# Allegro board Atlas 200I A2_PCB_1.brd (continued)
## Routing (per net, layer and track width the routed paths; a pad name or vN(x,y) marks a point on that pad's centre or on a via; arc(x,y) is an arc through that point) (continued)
V_3V3_USBHUB0: length 137.8
  TOP w0.203: C207.1 88.93,75 88.78,74.85 88.37,74.85 88.11,74.6 R467.1 ; 90.04,76.59 90.04,77.41 90.46,77.82 U36.73 ; U36.22 99.27,77.42 ; C206.1 97.16,85.95 96.06,85.95 95.35,85.24 U36.48 ; v1(92.89,74.55) 92.89,75.14 92.95,75.2 U36.4 92.95,76.18 93.25,76.48 ; v1(73.53,91.57) R547.2
  TOP w0.254: R460.1 88.16,70.05 88.37,69.85 v1(89.23,69.85) ; R460.1 R546.1 ; R460.1 88.54,70.36 88.75,70.56 88.75,72.87 88.27,73.36 88.27,74.14 R467.1 ; v1(96.16,90.04) 96.34,90.22 98.02,90.22 98.3,89.94 98.3,86.66 98.09,86.46 C206.1 ; 90.04,76.59 v1(90.04,76.07) 89.41,75.44 C207.1 ; C208.1 92.79,74.45 v1(92.89,74.55) ; 93.25,76.48 93.9,76.48 94.51,77.09 96.15,77.09 96.81,76.43 98.28,76.43 99.27,77.42 ; 88.27,90.32 94.01,90.32 ; v1(101.54,79.49) 101.38,79.32 R649.1
  TOP w0.381: R640.1 21.04,111.3 v1(21.05,111.3) ; 88.27,90.32 87.5,89.56 87.5,88.47 85.99,86.96 79.01,86.96 78.49,87.48 76.66,87.48 73.53,90.6 v1(73.53,91.57) ; R551.2 v1(105.26,85.7) ; 94.01,90.32 94.59,89.74 ; v1(82.63,69.22) 82.63,69.67 82.35,69.95 R643.1
  ART03 w0.381: v1(90.04,76.07) 90.04,75.03 90.53,74.55 v1(92.89,74.55) ; v1(66.37,96.74) 64.5,98.62 49.12,98.62 45.4,102.33 30.17,102.33 21.2,111.3 v1(21.05,111.3) ; v1(101.42,75.97) 101.54,76.09 v1(101.54,79.49)
  ART04 w0.381: v1(73.53,91.57) 72.62,92.48 70.64,92.48 v1(66.37,96.74)
  BOTTOM w0.381: v1(82.63,69.22) 83.26,69.85 v1(89.23,69.85)
  vias: v1(95.91,89.59) v1(103.68,93.4) v1(103.68,92.76) v1(104.67,74.68) v1(105.94,74.68)
V_5V0_HUB:
  vias: v1(83.85,106.68) v1(84.61,106.68) v1(93.65,104.04)
V_12V0_CON_IN_F: length 62.2
  TOP w0.254: v1(109.37,41.28) 109.24,41.14 R374.2 108.01,41.14 107.88,41.27 C226.1 106.91,41.27 106.38,40.74 106.38,40.56 106.09,40.28 U12.9
  TOP w0.381: R382.1 109.04,21.39 v1(108.58,21.85) ; R371.2 100.22,42.06 100.43,41.85 101.96,41.85 102.84,40.97 102.84,37.74 102.69,37.59 v1(102.69,36.02)
  ART03 w0.381: v1(102.69,36.02) 102.69,24.13 104.04,22.78 112.67,22.78 v1(113.16,22.3)
  BOTTOM w0.254: v1(109.37,41.28) 109.11,41.02 108.35,41.02 107.8,40.46 107.8,31.92 109.47,30.25 109.47,21.82 109.22,21.56 108.86,21.56 v1(108.58,21.85)
V_12V0_SENSE: length 26
  TOP w0.254: R380.2 109.29,40.33 v1(109.35,40.27)
  TOP w0.381: v1(108.58,20.92) 108.11,21.39 R382.2
  BOTTOM w0.254: v1(109.35,40.27) 109.08,40.54 108.45,40.54 108.18,40.27 108.18,32.08 109.86,30.4 109.86,21.66 109.38,21.18 108.84,21.18 v1(108.58,20.92)
  vias: v1(104.88,27.26) v1(104.88,25.99) v1(104.88,24.38) v1(106.15,27.26) v1(106.15,25.99) v1(106.15,24.38) v1(107.42,27.26) v1(107.42,25.99) v1(107.42,24.38)
V_AVDD_1V0_PHY0: length 4.8
  TOP w0.203: v1(12.78,49.81) 12.78,49.83 12.75,49.86 U1.9 ; v1(7.97,51.44) 8.33,51.79 U1.47 ; v1(10.69,49.81) 10.75,49.88 U1.4
  TOP w0.254: v1(12.78,49.81) C53.2 ; v1(7.97,51.44) C52.2 ; C56.2 10.69,49.35 v1(10.69,49.81)
  vias: v1(6.6,68.45) v1(7.44,68.43)
V_AVDD_1V0_PHY1: length 6.2
  TOP w0.203: U2.4 56.91,30.84 ; U2.9 58.91,30.84 ; U2.47 54.56,32.36
  TOP w0.254: v1(54.74,31.14) 54.43,31.45 C71.2 54.1,31.9 54.56,32.36 ; 56.91,30.84 v1(56.91,30.27) 56.91,30.01 C72.2 ; C73.2 59.49,29.69 v1(58.91,30.27) 58.91,30.84
  vias: v1(52.43,27.79)
V_AVDD_3V3_PHY0: length 11.8
  TOP w0.203: U1.12 14.44,50.71 ; v1(8.1,50.27) 9.35,50.27 9.55,50.47 U1.1
  TOP w0.254: C50.2 7.36,50.06 7.36,50.07 C49.2 8.02,50.34 v1(8.1,50.27) ; 14.44,50.71 14.61,50.54 v1(14.61,50.39) C51.2
  ART04 w0.254: v1(14.61,50.39) 14.27,50.73 8.56,50.73 v1(8.1,50.27)
V_AVDD_3V3_PHY1: length 18.1
  TOP w0.203: 60.41,31.29 U2.12 ; 54.74,30.07 55.04,30.07 55.71,30.75 U2.1
  TOP w0.254: 54.74,30.07 C76.2 C77.2 52.66,29.47 v1(52.4,29.21) 52.36,29.17 LB5.2 ; 60.41,31.29 v1(60.73,30.96) 62.08,30.96 C75.2
  ART03 w0.254: v1(60.73,30.96) 56.36,30.96 55.32,32 54.37,32 53.49,31.12 53.49,30.3 v1(52.4,29.21)
V_BAT_3V0: length 104.3
  TOP w0.254: J16.283 107.5,56.95 108.2,57.66 v1(108.71,57.66)
  TOP w0.381: D1.3 20.42,75.44 v1(20.43,75.43)
  ART04 w0.381: v1(64.57,61.35) 53,72.92 51.81,72.92 51.11,72.22 25.71,72.22 25.39,72.54 25.39,72.63 24.67,73.34 22.52,73.34 v1(20.43,75.43)
  BOTTOM w0.254: v1(64.57,61.35) 66.08,61.35 67.02,60.41 67.02,58.88 67.3,58.6 69.2,58.6 74.05,63.45 98,63.45 101.3,60.15 104.03,58.37 108,58.37 v1(108.71,57.66)
V_DV11_HUB: length 26.8
  TOP w0.203: U38.40 83.21,101.37 83.13,101.45 82.3,101.45 ; U38.12 92.25,98.97 92.05,99.17 ; v1(88.01,92.96) 88.29,93.24 U38.67 ; 91.09,101.92 U38.22 91.09,103.44 91.29,103.64 ; U38.61 85.89,93.17 85.69,92.96 v1(85.34,92.96) ; U38.70 89.49,94.45 v1(89.6,94.56) ; v1(82.93,97.54) 83.19,97.54 83.42,97.77 U38.49 ; U38.46 83.32,98.97
  TOP w0.254: 91.09,101.92 91.19,101.83 91.82,101.83 92.05,101.6 92.05,99.17 ; v1(82.93,97.54) 82.45,97.54 C331.1 ; 91.29,103.64 91.92,104.27 C334.1 ; v1(88.01,92.96) 88.01,92.96 88.01,92.33 ; v1(85.34,92.96) 85.27,92.89 85.27,92.33 ; 83.32,98.97 83.02,99.28 82.48,99.28 v1(82.16,99.59) 81.93,99.82 C330.1
  BOTTOM w0.381: v1(88.01,92.96) 88.75,93.7 92.71,93.7 93.04,93.37 93.04,92.91 93.5,92.46 95.86,92.46 v1(96.04,92.28)
  vias: v1(76.96,99.19) v1(76.96,97.92) v1(76.96,96.65) v1(76.96,95.38) v1(76.96,94.11) v1(76.96,92.84) v1(76.96,91.57) v1(76.96,90.3) v1(76.96,89.03) v1(96.71,99.16)
V_DV12_HUB: length 18.2
  TOP w0.203: U36.64 91.69,81.42 ; U36.50 94.55,84.18 94.68,84.05 94.83,84.05 94.95,84.17 U36.49 94.95,85.42 95.99,86.46 ; U36.3 92.55,75.36 92.35,75.16 ; U36.58 91.55,83.82 ; U36.7 94.15,74.98 v1(94.25,74.88) ; 91.5,79.02 U36.70
  TOP w0.254: 95.99,86.46 C227.1 96.87,86.46 v1(96.96,86.55) ; 91.55,83.82 92.24,83.13 92.24,81.57 v1(92.06,81.38) 91.73,81.38 91.69,81.42 ; C279.1 91.06,74.88 v1(91.34,75.16) 92.35,75.16 ; 91.5,79.02 91.73,78.79 v1(91.73,78.31)
  BOTTOM w0.381: v1(92.06,81.38) 92.68,80.75 92.68,78.77 92.23,78.31 v1(91.73,78.31)
  vias: v1(98.63,74.9) v1(99.9,74.9) v1(101.54,80.42) v1(102.21,79.07)
V_DV33_HUB: length 120
  TOP w0.203: v1(87,92.96) 87,93.17 87.09,93.26 U38.64 ; U38.52 83.39,96.57 83.19,96.77 v1(82.93,96.77) ; U38.6 92.01,96.57 v1(91.9,96.69) ; U38.15 v1(93.55,100.17) ; U38.58 84.69,93.2 v1(84.45,92.96) ; U38.29 88.29,103.05 ; 82.93,100.17 U38.43 ; U38.73 90.69,94.45 v1(90.81,94.56)
  TOP w0.254: LB20.2 92.86,107.24 91.85,108.25 90.25,108.25 89.38,107.39 R639.1 88.98,106.93 88.85,107.06 C332.2 88.47,107.06 88.14,106.73 88.14,106.05 88.52,105.66 R598.2 88.21,105.31 87.91,105 87.91,104.01 88.28,103.64 R651.1 88.57,103.33 88.29,103.05 ; 86.18,92.33 87.09,92.33 87.09,92.87 v1(87,92.96) ; 84.35,92.33 84.35,92.86 v1(84.45,92.96) ; C335.1 81.91,100.84 82.16,100.59 v1(82.16,100.36) 82.46,100.06 R652.2 82.93,100.17 ; C353.2 82.45,96.77 v1(82.93,96.77) ; R646.2 94.97,100.91 94.77,100.71 94.36,100.71 94.16,100.51 C327.2 93.6,100.12 v1(93.55,100.17)
  TOP w0.381: R576.2 R577.2 v1(79.38,104.78) ; R642.1 v1(31.62,118.24)
  ART03 w0.381: v1(82.16,100.36) 82.34,100.36 82.72,99.97 82.72,99.19 83.54,98.38 83.54,97.37 83.16,96.99 83.15,96.99 v1(82.93,96.77) ; v1(31.62,118.24) 32.56,118.24 36.07,114.73 36.07,114.5 36.16,114.42 36.16,108.55 36.27,108.43 36.27,108.18 39.88,104.57 46.29,104.57 49.17,101.69 66.84,101.69 69.93,104.78 v1(79.38,104.78) 83.11,108.51 87.46,108.51 87.82,108.15 89.64,108.15 90.57,109.08 91.7,109.08 92.52,108.26 92.52,107.97 95.33,105.15 96.98,105.15 v1(97.22,104.91)
  ART04 w0.381: v1(79.38,104.78) 79.38,104.13 82.16,101.34 v1(82.16,100.36)
  vias: v1(97.22,104.33)
V_DVDD_1V0_PHY0: length 4.8
  TOP w0.203: U1.22 16.1,54.99
  TOP w0.254: 16.1,54.99 16.34,54.99 v1(17.83,56.49) 18.08,56.74 C57.2
  vias: v1(9.6,68.43) v1(10.87,68.43)
V_DVDD_1V0_PHY1: length 38.3
  TOP w0.203: U2.22 61.4,35.56 62.3,36.47 C70.2
  TOP w0.254: C70.2 62.8,36.61 v1(63.3,37.11)
  ART03 w0.381: v1(50.25,28.55) 50.04,28.77 48.69,28.77 46.24,31.22 46.24,36.76 46.55,37.06 46.55,37.53 v1(45.97,38.1)
  BOTTOM w0.381: v1(45.97,38.1) 46.16,38.29 47.25,38.29 47.98,39.03 48.58,39.03 49.8,40.25 51.68,40.25 52.08,39.84 53.76,39.84 v1(55.65,41.73) 55.65,39.85 58.13,37.38 59.85,37.38 60.63,36.59 60.96,36.46 62.64,36.46 v1(63.3,37.11)
V_STBY_1V8: length 364.8
  TOP w0.203: C132.1 v1(117.66,81.93) ; R569.1 v1(70.35,71.01) ; v1(109.58,89.39) 109.58,89.38 R239.2 ; v1(73,73.05) 72.92,72.97 R568.1 ; v1(109.24,76.34) 109.27,76.32 109.86,76.32
  TOP w0.254: 88.16,118.59 88.67,118.59 v1(88.77,118.49) 89,118.26 U18.1 ; 88.16,118.59 R496.1 ; 88.16,118.59 C292.2 ; v1(117.66,81.93) 118.11,82.38 U35.1 ; U22.1 93.46,112.59 93.04,112.17 C136.2 v1(93.78,110.41) ; R396.2 89.24,37.45 U15.1 ; v1(54.61,66.04) 54.38,66.27 R88.1 R87.1 ; R464.2 v1(126.38,21.26) ; v1(92.2,44.35) 92.46,44.6 R703.1 R704.1 ; v1(46,37.29) 46.02,37.31 R116.1 ; R552.2 125.2,88.03 v1(125.22,88.01) ; U33.1 112.4,70.1 C304.1 ; J2.64 6.42,83.26 v1(5.85,82.69) ; Q2.2 55.05,96.45 v1(55.12,96.52) C83.2 R197.2 ; R571.1 R565.1 96.57,60.44 96.08,60.93 96.08,64 96.72,64.95 102.53,70.76 109.88,70.76 110.34,70.31 ; v1(100.2,114.05) R601.1 R602.1 100,115.06 100.31,115.37 R611.1 R610.1 100.31,117.79 101.11,118.59 v1(103.16,118.59) C138.2 103.32,117.98 103.87,117.43 U23.1 ; R553.2 120.76,79.22 v1(120.5,78.96) ; 110.77,58.14 C299.1 111.86,58.14 112.52,58.8 U32.1 ; v1(125.48,50.01) 127.91,47.57 133.38,47.57 133.78,47.17 133.78,43.58 R469.2 ; R591.2 115.19,67.55 v1(114.93,67.29) ; v1(2.54,106.05) 2.44,105.94 R49.2 ; R254.1 v1(125.81,42.16) ; R12.1 118.4,69.93 118.1,70.22 U21.1 ; v1(68.83,33.15) 68.83,35.03 R156.1 ; R466.2 v1(128.83,26.85) ; R497.1 88.75,115.09 89.1,115.44 92.42,115.44 v1(92.51,115.53) ; C298.1 118.43,58.56 U20.1 118.43,62.36 117.75,63.04 ; R354.2 v1(111.99,107.24) ; v1(125.58,24.86) 125.57,24.86 R15.1 ; v1(114.8,78.96) 115.06,79.22 R629.2 ; R347.2 v1(125.53,112.03) ; R239.2 108.71,88.77 108.48,88.54 108.48,86.49 109.83,85.14 111.89,85.14 112.4,84.62 U34.1 112.4,82.32 111.96,81.87 C131.1 ; R589.2 v1(125.2,64.66) ; R462.2 v1(128.83,32.44)
  TOP w0.381: R295.2 R294.2 R293.2 R292.2 126.09,58.12 v1(126.09,58.12) ; R66.2 4.11,106.17 4.67,106.73 6.1,106.73 ; R50.2 6.1,106.73 ; 6.1,106.73 7.32,106.73 7.87,106.17 v1(7.87,106.07) 7.72,105.92 R67.2 ; R12.1 C296.1 117.51,72.87 116.96,73.42 112.38,73.42 110.16,71.2 ; 110.57,70.87 111.25,70.87 111.66,70.46 111.66,69.95 C304.1 ; R80.1 22.23,88.32 21.49,89.05 20.65,89.05 20.14,89.56 20.14,90.35 v1(19.68,90.81) ; R42.1 v1(6.48,74.8)
  ART03 w0.254: v1(71.82,75.87) 72.92,74.77 72.92,73.66 73,73.58 v1(73,73.05) 72.65,72.71 72.58,72.71 72.08,72.21 70.74,72.21 70.35,71.83 v1(70.35,71.01) ; v1(111.99,107.24) 111.99,106.49 113.26,105.22 113.26,102.78 112.31,101.83 112.09,101.83 111.81,101.55 111.81,92.1 111.1,91.39 111.1,90.91 v1(109.58,89.39) ; v1(55.12,96.52) 53.57,98.07 48.85,98.07 45.16,101.77 29.72,101.77 26.46,105.03 21.49,105.03 21.23,104.78 17.99,104.78 15.8,106.96 3.45,106.96 v1(2.54,106.05)
  ART03 w0.381: v1(6.48,74.8) 6.48,76.09 5.96,76.6 5.96,82.58 v1(5.85,82.69)
  ART04 w0.254: v1(120.5,78.96) 120,78.45 117.92,78.45 117.41,78.96 v1(114.8,78.96) ; v1(128.83,26.85) v1(128.83,32.44) ; v1(54.61,66.04) 55.73,66.04 63.9,57.86 63.9,56.65 64.24,56.31 64.24,52.53 66.67,50.09 66.67,45.64 68.52,43.8 69.42,43.8 70.12,43.09 70.18,42.95 70.18,34.49 v1(68.83,33.15) ; v1(92.53,39.29) 92.53,39.74 92.2,40.07 v1(92.2,44.35)
  BOTTOM w0.254: 122.91,48.69 122.94,48.67 ; v1(109.58,89.39) 109.57,89.38 108.7,89.38 107.37,88.05 107.37,78.79 109.24,76.91 v1(109.24,76.34) ; 81.57,21.43 80.73,21.43 79.88,22.28 76.2,22.28 70.76,27.72 70.76,28.77 69.52,30.01 69.52,32.46 v1(68.83,33.15) 68.2,33.78 62.43,33.78 59.45,36.75 58.02,36.75 56.11,38.66 52.53,38.66 51.46,39.73 50.16,39.73 48.21,37.77 46.48,37.77 v1(46,37.29) ; v1(128.83,32.44) 127.58,32.44 ; 121.56,70.13 120.62,69.19 120.62,67.94 120.14,67.46 120.14,67.03 119.46,66.34 115.87,66.34 v1(114.93,67.29)
  vias: v1(72.14,86.59) v1(72.77,86.59) v1(91.26,39.29) v1(91.89,39.29) v1(123.57,50.01) v1(124.21,50.01) v1(124.84,50.01) v1(127.74,34.82) v1(128.3,34.82)
V_STBY_3V3: length 228.6
  TOP w0.254: C300.2 117.41,67.27 v1(118.44,67.27) 118.44,65.91 U20.14 ; R113.2 122.17,104.32 122.17,103.7 R484.1 R483.1 R485.1 122.28,100.91 124.28,100.91 124.43,100.76 ; v1(48.44,29.79) 48.31,29.67 R647.2 ; v1(111.83,29.75) R34.2 R33.2 ; C17.2 75.74,82.43 U25.14 78.58,82.43 78.97,82.04 ; C137.1 v1(110.17,118.36) 110.17,117.69 109.92,117.43 U23.8 ; v1(100.22,118.38) R494.2 R495.2 99.47,117.33 R489.1 ; R236.1 R238.1 124.97,77.23 v1(125.09,77.36) ; U32.14 112.52,66.65 v1(111.89,67.29) 111.43,67.75 111.43,68.36 C301.2 ; C16.2 113.08,38.51 112.83,38.25 R24.2 ; J10.51 v1(2.05,73.65) ; C133.1 88.6,111.53 v1(88.7,111.63) 89.51,111.63 89.96,112.08 U22.8 ; C140.2 117.21,78.94 v1(118.11,78.94) 118.11,77.58 U21.14 ; R41.1 5.61,74.14 v1(4.82,73.35) J10.50 ; C129.2 v1(111.2,87.25) 111.73,87.25 112.4,87.92 U34.14 ; U19.24 110.96,92.09 C293.1 ; C291.1 95.77,118.38 v1(95.76,118.36) 95.65,118.26 U18.8 ; 78.97,82.04 78.97,78.91 78.61,78.55 78.61,77.11 78.01,76.51 U24.14 75.62,76.51 C139.2 ; 78.97,82.04 78.97,85.93 78,86.89 76.05,86.89 v1(75.39,87.55) ; J10.45 v1(2.05,71.85) ; R64.1 v1(125.2,62.63) ; v1(113.72,100.74) C290.1 113.97,101.35 114.24,101.61 U17.8 ; v1(125.22,74.47) 124.97,74.22 124.97,73.99 124.57,73.59 R65.1 ; R36.2 v1(125.11,67.06) ; C130.2 118.1,90.59 v1(118.12,90.61) 118.12,89.25 U35.14 ; v1(86.57,114.14) 87.26,114.14 R594.1 R600.2 R599.2 ; R608.2 R609.2 R603.1 111.59,114.6 v1(111.54,114.55) ; R32.2 v1(113.55,33.99) ; R648.2 v1(59.54,15.11) ; U33.14 112.41,77.58 v1(112.41,78.94) 111.42,78.94 C303.2
  TOP w0.381: LB8.2 99.5,20.16 v1(99.39,20.27) ; R251.2 v1(97.28,35.97) ; Q3.2 38.8,113.96 C84.2 R199.2 v1(39.37,112.39) ; v1(109.07,92.1) 109.15,92.02 C294.1 C293.1 ; 112.69,45.57 110.77,45.57 109.73,44.53 107.62,44.53 106.63,45.52 105.13,45.52 R478.2 R480.2 105,43.84 103.99,42.82 101.07,42.82 100.46,43.43 U16.5 98.6,43.43 C288.1 ; R48.2 17.73,89.94 v1(17.68,89.89) ; v1(79.38,19.02) R384.2
  TOP w0.508: v1(130.49,60.32) 130.62,60.45 J11.1 ; J11.17 v1(130.08,80.77)
  ART03 w0.254: v1(125.11,67.06) 126.45,68.4 126.45,73.24 v1(125.22,74.47)
  ART03 w0.381: v1(92.03,32.84) 93.78,34.59 95.91,34.59 v1(97.28,35.97) ; v1(79.38,19.02) 80.77,17.63 82.07,17.63 82.88,16.82 82.88,16.05 84.09,14.85 93.48,14.85 94.68,16.04 94.68,19.22 90.76,23.14 v1(90.76,32.21)
  BOTTOM w0.254: v1(68.83,31.6) 68.74,31.6 67.78,32.55 60.37,32.55 59.8,31.98 56.15,31.98 55.7,32.43 55.7,33.4 52.17,36.93 49.53,36.93 48.54,35.94 47.43,35.94 47.02,35.53 44.85,35.53 44.28,34.97 44.28,31.21 45.44,30.05 46.35,30.05 46.61,29.79 v1(48.44,29.79) ; v1(59.54,15.11) 59.53,15.1 57.63,13.2 57.63,12.09 58.77,10.95 68.91,10.95 72.85,14.88 77.95,14.88 79.38,16.31 v1(79.38,19.02)
  vias: v1(0.89,48.01) v1(0.89,47.37) v1(2.54,85.72) v1(2.54,84.45) v1(24.13,84.45) v1(24.13,83.19) v1(43.18,115.57) v1(44.45,115.57) v1(57.4,44.75) v1(57.4,44.12) v1(68.83,32.18) v1(88.7,110.36) v1(89.31,110.36) v1(90.76,32.84) v1(91.4,32.84) v1(91.4,32.21) v1(92.03,32.21) v1(98.53,19.96) v1(98.53,19.33) v1(103.76,71.86) v1(104.52,71.86) v1(107.67,98.53) v1(107.67,97.89) v1(107.67,97.26) v1(107.67,96.62) v1(107.67,95.99) v1(108.43,92.1) v1(113.92,27.43) v1(113.92,26.82) v1(114.1,45.11) v1(114.1,44.48) v1(117.86,55.02) v1(118.49,55.02) v1(119.13,55.02) v1(119.76,55.02) v1(125.07,98.98) v1(125.07,98.35) v1(125.07,97.71) v1(125.07,97.08) v1(125.07,96.44) v1(128.42,40.18) v1(128.42,39.62)
V_STBY_5V0: length 22.8
  TOP w0.254: v1(49.02,31.37) 49.02,31.75 48.62,32.15 R274.1 ; C126.2 58.3,22.43 59.46,22.43 59.97,21.92 59.97,21.21 60.18,21 R277.1 ; v1(79.39,20.51) 78.52,20.51 R391.2
  BOTTOM w0.254: 77.09,6.99 77.09,11.94 80.06,14.91 80.06,19.84 v1(79.39,20.51)
  vias: v1(45.29,34.92) v1(45.29,34.29) v1(56.41,20.37) v1(56.41,19.74) v1(68.2,26.97) v1(68.2,26.39) v1(68.2,25.81) v1(69.39,28.27) v1(69.39,27.76) v1(74.88,3.71) v1(75.51,3.71) v1(76.15,3.71) v1(101.85,101.42) v1(103.12,101.42) v1(104.39,101.42) v1(126.32,61.57) v1(126.9,61.57) v1(127.49,61.57) v1(130.32,34.74) v1(130.32,34.23) v1(130.32,33.72) v1(130.32,33.22)
V_STBY_12V0: length 28
  TOP w0.254: R388.2 88.9,19.02 88.96,18.97 v1(88.98,18.97) ; R370.2 108.95,35.6 108.64,35.28 105.67,35.28 D41.1 ; v1(109.74,114.65) 109.25,114.15 R11.1
  ART03 w0.254: v1(109.74,114.65) 109.74,113.68 112.33,111.08 v1(113.89,111.08) ; v1(78.23,23.47) 78.64,23.47 80.82,21.29 82.09,21.29 83.95,19.43 88.43,19.43 88.62,19.24 88.71,19.24 v1(88.98,18.97)
  vias: v1(27.56,54.56) v1(27.66,50.22) v1(28.19,54.56) v1(28.3,50.22) v1(28.83,54.56) v1(28.93,50.22) v1(29.46,54.56) v1(29.57,50.22) v1(36.09,45.72) v1(36.73,45.72) v1(37.36,45.72) v1(38,45.72) v1(38.63,45.72) v1(39.27,45.72) v1(39.9,45.72) v1(77.6,24.1) v1(77.6,23.47) v1(78.23,24.1) v1(103.71,33.5) v1(103.71,32.87) v1(103.71,32.23) v1(103.71,31.6) v1(104.34,33.5) v1(104.34,32.87) v1(104.34,32.23) v1(104.34,31.6) v1(113.89,109.81) v1(127.7,110.67) v1(127.7,110.09) v1(128.29,110.67) v1(128.29,110.09) v1(128.87,110.67) v1(128.87,110.09) v1(133.22,29.67) v1(133.22,29.03) v1(133.22,28.4) v1(133.22,27.76)
V_VCC_1V8_EMMC: length 17.2
  TOP w0.127: U27.P5 U27.N4 U27.P3
  TOP w0.203: v1(6.35,93.93) 6.63,93.93 7.06,93.49 U27.C6
  TOP w0.254: R209.1 v1(40.83,79.48) ; R210.1 v1(39.54,79.48) ; Q2.3 56.01,92.2 55.7,91.9 C89.2 ; R206.1 16.12,86.25 15.72,85.85 12.52,85.85 v1(12.01,86.36) R205.1 R207.1 ; R208.1 v1(42.11,79.48) ; R202.1 v1(44.69,79.48) ; U27.P3 8.56,99.24 v1(9.02,99.69) ; R211.1 v1(38.25,79.48) ; U27.M4 U27.N4 ; R203.1 v1(45.97,79.48)
  TOP w0.381: R204.1 8.74,86.97 v1(8.74,86.36)
  vias: v1(34.16,89.36) v1(34.8,89.36) v1(56.87,93.65) v1(57.51,93.65)
V_VCC_3V3_BUF: length 7
  TOP w0.254: R316.1 71.78,115.21 v1(71.6,115.04) ; 67.69,118.24 v1(66.93,118.24) ; U10.42 57.05,115.65 v1(56.95,115.75) 56.74,115.95 C152.1 ; v1(66.04,112.39) 65.91,112.52 C161.1 65.68,113.13 65.17,113.65 U10.15 ; R322.1 v1(52.32,114.17) ; R344.1 v1(66.93,115.65)
  vias: v1(46.99,111.12) v1(48.26,111.12)
V_VCC_3V3_EMMC: length 17.5
  TOP w0.254: 7.06,94.92 U27.E6 ; 7.06,94.92 7.07,94.91 U27.F5 ; 7.06,94.92 v1(6.9,95.08) ; U27.K9 5.56,96.42 5.57,96.41 ; 5.57,96.41 v1(5.71,96.27) ; 5.57,96.41 U27.J10
  TOP w0.381: U4.5 23.24,103.89 v1(23.5,104.14) ; C91.2 35.33,116.12 C101.2 ; U3.5 v1(18.67,98.3) 18.67,97.41 17.67,96.41 J3.4
  BOTTOM w0.254: v1(18.67,98.3) 18.67,99.78 23.03,104.14 v1(23.5,104.14)
  vias: v1(32.38,116.84) v1(32.38,115.57)
V_VCCO_3V3_BUF: length 5.9
  TOP w0.254: v1(60.32,110.28) 60.31,110.28 C157.1 59.58,110.45 60.46,111.33 U10.5 ; U10.8 v1(61.96,110.63) ; U10.45 57.03,114.15 v1(56.9,114.27) 56.44,114.73 C158.1
  vias: v1(52.45,117.73) v1(53.72,117.73)
V_VDD_3V3_PHY0: length 50.6
  TOP w0.203: U1.30 11.95,57.61 ; 11.55,57.56 U1.31
  TOP w0.254: R126.1 v1(25.93,72.77) R99.1 ; LB16.2 34.36,28.45 v1(34.36,28.46)
  TOP w0.381: 22.67,61.09 23.52,61.09 23.52,61.57 23.01,62.08 R98.1 v1(22.1,62.08)
  ART03 w0.254: v1(25.93,72.77) 25.93,70.76 22.81,67.64 22.81,62.79 v1(22.1,62.08)
  BOTTOM w0.254: 15.21,47.88 16.71,46.38 16.71,44.78 27.79,33.71 31.95,33.71 34.72,30.93 34.72,28.82 v1(34.36,28.46)
  vias: v1(5.59,48.03) v1(5.92,48.48) v1(9.65,60.01)
V_VDD_3V3_PHY0_LED: length 50.4
  TOP w0.203: v1(4.24,16.38) C92.1
  TOP w0.254: v1(29.59,21.08) 29.59,24.09 30.75,25.25 30.97,25.25 32.02,26.31 32.02,26.91 32.8,27.69 LB16.1
  BOTTOM w0.254: v1(29.59,21.08) 29.59,14.39 23.55,8.35 14.18,8.35 J17.20 11.43,6.63 7.65,10.41 7.65,12.98 v1(4.24,16.38)
V_VDD_3V3_PHY1: length 67.6
  TOP w0.254: v1(50.62,39.24) R154.1 R153.1 51.05,40.13 50.67,40.51 50.67,41.38 51.05,41.76 51.05,42.57 51.89,43.41 52.93,43.41 v1(53.04,43.31) 53.26,43.08 R155.1 53.67,42.7 53.83,42.85 R192.1 ; R194.1 v1(66.52,32) ; LB17.2 v1(35,24.64)
  ART03 w0.381: v1(50.62,39.24) 47.41,36.03 47.41,31.57 48.03,30.95 48.56,30.95 v1(50.18,29.34)
  ART04 w0.254: v1(57.89,38.48) 57.89,38.61 53.19,43.31 v1(53.04,43.31)
  ART04 w0.305: v1(66.52,32) 65.28,33.24 65.28,35.21 64.64,36.75 64.64,37.55 63.99,38.21 61.28,38.21 59.97,39.52 58.93,39.52 v1(57.89,38.48)
  BOTTOM w0.254: v1(35,24.64) 36.4,24.64 40.15,28.39 40.15,30.75 43,33.6 43,34.91 44.49,36.4 46.66,36.4 47.07,36.8 48.19,36.8 v1(50.62,39.24)
V_VDD_3V3_PHY1_LED: length 24.6
  TOP w0.254: C93.1 32.21,23.11 32.92,23.82 v1(32.92,24.13) 33.43,24.64 LB17.1
  BOTTOM w0.254: J17.24 13.96,21.89 22.14,21.89 J17.22 24.76,24.51 32.54,24.51 v1(32.92,24.13)
V_VDDI_EMMC: length 15.3
  TOP w0.127: U27.B1 U27.C2
  TOP w0.254: U27.B1 9.7,92.91 10.13,92.48 10.49,92.48 v1(10.71,92.25)
  TOP w0.381: C88.1 8.63,103.92 v1(8.86,103.69)
  ART03 w0.381: v1(10.71,92.25) 10.71,100.62 8.86,102.48 v1(8.86,103.69)
XTAL_IN_PHY0: length 8.8
  TOP w0.203: X1.1 3.84,55.55 4.04,55.75 C46.1 4.16,55.38 4.42,55.12 6.39,55.12 R105.1 7.13,54.81 7.33,54.61 7.33,53.09 7.83,52.59 U1.45
XTAL_IN_PHY1: length 6.5
  TOP w0.203: U2.45 53.95,33.16 R172.1 53.71,33.74 52.31,35.14 C64.1 51.18,34.98 51.18,34.87 50.2,33.9 X2.1
XTAL_OUT_PHY0: length 2.2
  TOP w0.203: U1.46 7.46,52.19 7.36,52.3 R106.1
XTAL_OUT_PHY1: length 1.4
  TOP w0.203: U2.46 53.93,32.76 R142.1
$7N42484: length 8.2
  TOP w0.203: U1.48 8.69,51.39 8.2,50.9 5.81,50.9 5.33,50.42 3.05,50.42 2.41,51.05 R91.2
$7N42485: length 7.5
  TOP w0.203: R128.2 18.63,50.58 17.02,52.19 U1.15
$7N42486: length 15.9
  TOP w0.203: R102.1 v1(7.47,69.24) ; v1(7.33,57.53) 7.97,56.9 7.97,55.88 8.45,55.39 U1.38
  ART03 w0.203: v1(7.33,57.53) 8.08,58.28 8.08,68.62 v1(7.47,69.24)
$7N42487: length 2.7
  TOP w0.203: U1.39 8.35,54.99 7.59,55.75 7.59,56.13 7.22,56.51 R89.1
$7N42488: length 2.3
  TOP w0.203: R104.1 7.04,55.65 8.1,54.59 U1.40
$7N42489: length 21.4
  TOP w0.203: v1(7.84,53.47) 7.84,53.72 8.31,54.19 U1.41 ; R103.1 v1(8.11,70.88)
  ART03 w0.203: v1(8.11,70.88) 6.15,68.92 6.15,66.65 6.11,66.62 6.11,63.28 5.74,62.9 5.74,55.57 v1(7.84,53.47)
$7N42494: length 28.7
  TOP w0.203: R129.2 24.56,70.48 v1(24.43,70.36) 24.31,70.48 C45.2 ; U1.14 15.36,51.79 16.23,51.43 17.51,50.58 v1(17.95,50.39)
  ART03 w0.203: v1(17.95,50.39) 16.99,51.35 16.99,55.96 17.09,56.06 17.09,56.97 16.99,57.07 16.99,59.56 17.91,60.48 17.91,63.83 v1(24.43,70.36)
$7N42503: length 23.8
  TOP w0.203: v1(14.1,62.15) 14.43,61.82 19.66,61.82 20.4,61.09 21.81,61.09 ; U1.34 10.35,57.01 9.88,57.48 9.56,57.48 9.02,58.01 6.82,58.01 6.57,57.76 v1(6.57,57.53)
  ART03 w0.203: v1(6.57,57.53) 7.11,57 9.04,57 9.42,57.38 10.82,60.76 11.36,61.3 13.43,62.15 v1(14.1,62.15)
$7N42505: length 68.4
  TOP w0.203: R93.1 46.69,38.18 R116.2 ; R119.1 17.78,48.51 v1(17.78,48.51) ; R96.1 42.57,39.75 41.27,41.05 36.22,41.05 35.76,40.59 R115.2 35.26,40.69 34.8,41.15 32.38,41.15 31.88,41.66 31.88,45.09 32.13,45.34 v1(32.38,45.34) ; v1(23.76,67.72) 24.26,68.23 R118.1
  TOP w0.254: R95.1 R94.1 R93.1 R90.1 R92.1 R96.1
  ART03 w0.203: v1(23.76,67.72) 23.37,67.33 23.37,61.74 20.05,58.42 19.83,58.42 18.29,56.88 18.29,56.3 18.03,56.05 18.03,51.17 18.56,50.65 18.56,49.93 17.78,49.15 v1(17.78,48.51) 18.67,48.51 19.56,49.4 19.81,49.4 20.45,50.04 20.45,51.49 20.65,51.69 24.13,51.69 26.26,49.56 28.98,49.56 32.38,46.15 v1(32.38,45.34)
$7N42508: length 4
  TOP w0.203: C47.2 5.29,51.31 X1.3 5.65,52.41 6.34,53.11 R106.2 R105.2
$7N63401: length 1.9
  TOP w0.155: R137.1 9.49,49.31 10.35,50.17 U1.3
$7N63402: length 6.5
  TOP w0.155: U1.6 11.55,50.38 11.53,50.36 11.53,47.63 10.82,46.91 9.14,46.91 8.99,46.76 8.99,46.53 R130.1
$7N63403: length 6.7
  TOP w0.155: U1.5 11.15,47.78 10.66,47.29 8.98,47.29 8.43,46.74 8.43,46.48 8.28,46.33 R131.1
$7N63404: length 4.8
  TOP w0.155: U1.8 12.35,50.26 12.27,50.17 12.27,47.22 11.66,46.61 11.66,46.31 R132.1
$7N63405: length 5
  TOP w0.155: U1.7 11.95,50.4 11.89,50.33 11.89,47.4 10.74,46.25 R133.1
$7N63406: length 2.7
  TOP w0.155: U1.11 13.55,50.25 13.74,50.06 13.74,48.25 R134.1
$7N63407: length 3.8
  TOP w0.155: R135.1 13.36,47.72 13.36,49.91 13.17,50.09 13.17,50.1 13.15,50.12 U1.10
$7N63408: length 2.3
  TOP w0.155: U1.2 9.95,50.31 9.31,49.66 9.06,49.66 R136.1
$8N37110: length 2.5
  TOP w0.203: R169.2 54.84,30.51 55.31,30.97 55.31,31.31 55.03,31.58 U2.48
$8N37111: length 8
  TOP w0.203: U2.15 61.85,32.76 62.15,32.47 63.56,32.47 64.03,32.94 64.03,34.95 64.24,35.16 64.24,36.35 64.63,36.74 R182.2
$8N37112: length 6.9
  TOP w0.203: R165.1 49.76,37.5 50.53,38.28 52.73,38.28 53.87,37.13 53.87,36.63 54.54,35.96 U2.38
$8N37113: length 4
  TOP w0.203: R164.1 52.65,37.72 53.21,37.16 53.21,36.68 54.33,35.56 U2.39
$8N37114: length 6.5
  TOP w0.203: U2.40 54.09,35.16 52.73,36.53 52.73,36.88 52.53,37.08 50.55,37.08 50.04,36.58 R167.1
$8N37115: length 3.5
  TOP w0.203: R166.1 53.88,34.76 U2.41
$8N37120: length 7.9
  TOP w0.203: U2.14 61.62,32.36 61.87,32.11 64.29,32.11 v1(64.35,32.04) 64.35,32.27 64.44,32.36 64.44,34.57 64.87,35 C68.2 R183.2
$8N37128: length 4.5
  TOP w0.203: U2.34 56.51,37.87 55.86,38.52 54.89,38.52 54.41,39.01 v1(54.41,39.31) 54.41,39.62 R168.2
$8N37132: length 3.9
  TOP w0.203: R172.2 R142.2 52.9,32.28 52.58,31.96 X2.3 51.66,30.96 C65.2
$8N37208: length 14.2
  TOP w0.203: R149.1 67.77,40.23 67.44,39.9 v1(67.44,38.13) ; R156.2 R175.1 ; R151.1 67.33,37.6 R174.1
  TOP w0.254: R148.1 v1(61.89,41.63) R152.1 ; R157.2 59.61,39.62 59.61,39.02 v1(59.61,39.02) ; v1(67.44,38.13) R174.1 68.07,37.49 68.33,37.24 R175.1 ; R147.1 v1(65.61,41.63) R150.1
$8N49706: length 4.4
  TOP w0.155: U2.3 56.51,31 56.49,30.98 56.49,30.48 55.04,29.03 55.04,28.2 55.23,28.02 R191.1
$8N49707: length 4.2
  TOP w0.155: U2.6 57.71,30.62 57.73,30.61 57.73,29.25 56.77,28.3 56.77,27.82 R184.1
$8N49708: length 4.2
  TOP w0.155: R185.1 56.39,27.82 56.39,28.45 57.35,29.41 57.35,30.45 57.33,30.46 57.33,30.91 57.31,30.93 U2.5
$8N49709: length 4.1
  TOP w0.155: R186.1 58.93,27.87 58.93,28.7 58.48,29.15 58.48,30.7 58.51,30.74 U2.8
$8N49710: length 4
  TOP w0.155: R187.1 58.55,27.77 58.55,28.54 58.1,28.99 58.1,30.86 58.11,30.87 U2.7
$8N49711: length 4.7
  TOP w0.155: R188.1 61.18,27.81 61.18,29.72 60.27,30.63 59.85,30.63 59.71,30.77 U2.11
$8N49712: length 4.7
  TOP w0.155: R189.1 60.8,27.82 60.8,29.57 60.12,30.25 59.69,30.25 59.31,30.63 U2.10
$8N49713: length 4.5
  TOP w0.155: U2.2 56.11,30.64 54.66,29.18 54.66,28.19 54.32,27.85 R190.1
$9N34271: length 9.4
  TOP w0.203: R214.1 C83.1 R197.1 56.62,98.07 56.96,97.72 Q2.1 56.96,94.84 56.46,94.34 55.3,94.34 54.86,93.9 R196.1
$9N34273: length 1
  TOP w0.203: C91.1 R198.2
$9N34274: length 7.4
  TOP w0.203: Q5.1 42.3,114.08 R201.2 C85.1 40.34,115.47 40.03,115.77 40.03,117.12 40.44,117.53 R1.2 R2.2
$9N34275: length 5.6
  TOP w0.203: R215.2 36.45,111.99 36.93,111.51 41,111.51 Q5.3
$9N34276: length 5.4
  TOP w0.203: C84.1 36.55,113.41 R215.1 ; C84.1 R199.1 ; C84.1 36.89,113.96 Q3.1 36.49,114.43 R198.1
$9N34313: length 1
  TOP w0.203: C89.1 54.89,91.92 R196.2
$9N34316: length 3.7
  TOP w0.203: R212.2 R213.2 C90.1 52.64,99.76 Q4.1
$9N34317: length 2.4
  TOP w0.203: Q4.3 51.84,97.26 R214.2
$12N40858: length 2.6
  TOP w0.203: R306.2 C118.1 R307.2 R245.2
$12N40901: length 2.8
  TOP w0.203: 99.45,10.72 99.45,10.05 R245.1 ; 99.45,10.72 99.67,10.72 R244.1 ; 99.45,10.72 D5.1
$12N40902: length 3
  TOP w0.203: R247.1 R248.2 99.37,22.63 U7.3
$12N40903: length 1.7
  TOP w0.203: R249.1 96.83,22.06 U7.1
$12N40904: length 18.3
  TOP w0.203: R250.2 96.27,33.26 Q8.1 97.63,33.04 v1(97.76,33.18) ; R249.2 97.02,20.31 v1(96.9,20.19)
  ART03 w0.203: v1(96.9,20.19) 95.38,21.72 95.38,30.79 v1(97.76,33.18)
$12N40909: length 3.6
  TOP w0.203: R251.1 R259.1 98.3,33.71 98.77,33.24 Q8.3
$12N55490: length 1.7
  TOP w0.188: U5.3 109.43,15.77 109.72,16.06 109.72,16.54 C308.1
$12N55491: length 1.8
  TOP w0.188: U5.4 108.93,15.81 109.33,16.22 109.33,16.45 C310.1
$12N56522: length 1.9
  TOP w0.381: D7.2 102.29,20.02 102.14,20.16 LB8.1
$12N60383: length 1.8
  TOP w0.203: R242.2 110.82,16.58 109.93,15.69 U5.2
$12N71093: length 5.2
  TOP w0.203: U7.5 100.64,26.72 101.45,25.91 R14.1 R18.2
$12N71230: length 3.8
  TOP w0.203: U7.7 98.1,27.65 98.24,27.51 99.16,27.51 99.37,27.71 U7.6
$13N103139: length 1.1
  TOP w0.254: U8.1 46.14,30.84 LB9.1
$13N103140: length 1.4
  TOP w0.203: R272.1 46.84,29.67 R273.2
$13N103141: length 0.9
  TOP w0.203: R273.1 U8.2
$13N103146: length 1.1
  TOP w0.254: LB10.1 57.26,16.29 U9.1
$13N103147: length 1.4
  TOP w0.203: R275.1 58.9,14.15 57.94,15.11 R276.2
$13N103148: length 0.9
  TOP w0.203: R276.1 U9.2
$16N50509: length 4.5
  TOP w0.254: MIC1.2 131.47,37.19 D27.2 131.47,38.95 131.73,39.21 132.44,39.21 132.69,38.96 132.69,38.51 132.84,38.36 LB12.1
$16N50739: length 2.2
  TOP w0.203: MIC1.1 131.59,36.12 R314.1 C147.1
$17N15518: length 4.2
  TOP w0.203: R321.2 67.03,114.83 66.67,115.19 65.92,115.19 65.38,114.65 ; 65.38,114.65 65.38,114.4 65.12,114.15 U10.16 ; 65.38,114.65 U10.17
$17N15519: length 4.9
  TOP w0.203: U10.38 57.41,117.65 56.74,118.31 55.02,118.31 53.8,117.09 R319.2
$17N15520: length 4.6
  TOP w0.203: R315.2 54.23,116.1 54.97,115.36 56.61,115.36 57.33,114.65 U10.44
$17N15521: length 7.8
  TOP w0.203: R320.2 52.1,115.54 54.2,115.54 54.66,115.08 54.66,114.17 55.19,113.65 U10.46
$17N51906: length 1.8
  TOP w0.203: U10.41 57.26,116.15 56.57,116.84 R114.2
$17N51968: length 2
  TOP w0.203: R170.2 56.38,117.69 57.42,116.65 U10.40
$17N56555: length 8.1
  TOP w0.203: v1(80.87,114.02) 80.87,114.02 80.87,115.09 VCXO1.1 ; OSC1.1 84.96,115.18 R4.2
  TOP w0.254: v1(84.95,112.95) 84.95,113.64 R4.2
  ART04 w0.203: v1(84.95,112.95) 81.95,112.95 v1(80.87,114.02)
$17N57348: length 11.2
  TOP w0.203: VCXO1.3 76.3,117.68 v1(76.02,117.96) 75.7,118.28 R3.1 ; OSC1.3 83.12,117.74 83.12,118.62 v1(83.12,118.62)
  ART04 w0.203: v1(83.12,118.62) 82.47,117.96 v1(76.02,117.96)
$17N59162: length 5.2
  TOP w0.203: C15.2 R341.2 R342.2 67.64,117.37 R340.2 65.97,117.37 65.24,116.65 U10.21
$18N13056: length 8.2
  TOP w0.203: D31.1 123.57,112.47 v1(123.57,112.47)
  TOP w0.381: R355.2 123.91,111.4 D31.1
  ART03 w0.203: J8.3 122.33,114.68 122.33,113.72 v1(123.57,112.47)
$18N13057: length 3.7
  TOP w0.203: R346.2 126.26,111.4 126.05,111.2 126.05,110.79 125.85,110.59 R347.1 R355.1
  TOP w0.381: R355.1 123.91,110.59 D31.2
$18N13061: length 0.8
  TOP w0.203: D29.2 R350.1
$18N13062: length 3
  TOP w0.203: D29.1 R351.1 116,104.67 C309.2
$18N13063: length 1.3
  TOP w0.203: Q10.1 117.55,104.65 117.5,104.6 R351.2
$19N38557: length 6.3
  TOP w0.508: T19.1 v1(14,35.54) ; T19.7 v1(8,38.53) ; T19.4 11,38.87 ; T19.10 v1(5,35.54)
$19N42379: length 4.5
  TOP w0.508: T20.7 v1(23.93,38.51) ; T20.10 v1(20.93,38.51) ; T20.4 v1(26.93,38.51)
  vias: v1(29.72,40.21) v1(29.72,38.94)
$19N46347: length 50
  TOP w0.203: R365.1 33.1,26.67 31.25,24.82 30.99,24.82 30.35,24.18 v1(30.35,21.08) ; C201.1 v1(4.24,15.37)
  BOTTOM w0.203: J17.19 16.09,7.72 23.62,7.72 30.15,14.24 30.15,20.88 v1(30.35,21.08)
  BOTTOM w0.254: J17.19 13.91,5.54 11.58,5.54 7.19,9.93 7.19,12.42 v1(4.24,15.37)
$19N48969: length 9.1
  TOP w0.203: C204.1 32.92,22.94 v1(32.92,23.11) 33.43,23.62 R368.1
  BOTTOM w0.203: J17.21 32.64,23.39 v1(32.92,23.11)
$19N48970: length 21
  TOP w0.203: R367.1 33.43,25.65 v1(32.92,25.15) 32.08,24.31 C203.1
  BOTTOM w0.203: J17.23 16.75,25.15 v1(32.92,25.15)
$19N66318: length 13
  TOP w0.508: T19.24 v1(14,29.37) ; T19.21 v1(11,29.37)
  BOTTOM w0.381: v1(14,29.37) 14,29.76 13.64,30.12 11.33,30.12 11,29.8 v1(11,29.37) 11,29.14 v1(6.96,25.1)
$19N66421: length 38.4
  TOP w0.508: T20.18 v1(23.93,29.37) ; T20.24 v1(29.93,29.37) ; T20.21 v1(26.93,29.37) ; T20.15 v1(20.93,29.37)
  BOTTOM w0.254: 26.44,27.18 23.52,27.18 ; 26.44,27.18 26.93,27.67 v1(26.93,29.37) ; 26.44,27.18 29.54,27.18 29.93,27.57 v1(29.93,29.37) ; 23.52,27.18 20.12,27.18 ; 23.52,27.18 23.93,27.59 v1(23.93,29.37) ; 20.12,27.18 12.45,27.18 9.09,23.83 v1(9.09,22.81) ; 20.12,27.18 20.93,27.99 v1(20.93,29.37)
$19N73517: length 23.6
  TOP w0.203: R366.1 33.43,22.61 v1(32.92,22.1) 32.92,21.5 32.5,21.08 C202.1
  BOTTOM w0.203: J17.18 24.98,7.97 28.19,7.97 30.63,10.41 30.63,18.86 32.92,21.15 v1(32.92,22.1)
$20N78412: length 6.7
  TOP w0.203: R374.1 108.25,42.16 106.32,42.16 106.17,42.32 R369.1 105.82,41.86 105.56,41.61 104.34,41.61 104.14,41.4 104.14,40.98 104.34,40.78 U12.10
$20N78416: length 0.9
  TOP w0.203: R378.1 97.05,39.21 R379.2
$20N78420: length 4.1
  TOP w0.203: C212.1 C219.1 99.29,38.1 99.49,38.3 99.49,38.91 99.86,39.28 U12.4
$20N78421: length 3.3
  TOP w0.203: C221.1 R378.2 99.05,39.21 99.62,39.78 U12.3
$20N78422: length 1
  TOP w0.203: C213.2 R375.1
$20N78423: length 4.5
  TOP w0.203: R370.1 107.89,37.59 C215.1 107.81,37.59 R376.2 106.15,38.19 106.15,38.57 105.94,38.78 U12.6
$20N78424: length 4.3
  TOP w0.203: R371.1 C214.2 R377.2
  TOP w0.254: U12.2 99.63,40.28 99.26,40.64 R371.1
$20N78430: length 3.5
  TOP w0.254: U12.8 106.45,39.78 106.55,39.88 C226.2 107.65,39.88 108.01,39.52 R380.1
$20N81774: length 2.2
  TOP w0.381: R381.2 102.62,29.85 Q11.4
$20N97792: length 1.1
  TOP w0.381: R383.1 C211.2
$20N102271: length 2.8
  TOP w0.203: U26.4 112.06,109.95 111.86,109.74 111.86,108.71 112.53,108.03 R357.1
$20N102272: length 1
  TOP w0.203: R356.1 R357.2
$20N102276: length 2.8
  TOP w0.203: U26.2 111.8,110.95 110.72,112.02 C321.2
$20N112363: length 5.1
  TOP w0.203: U26.3 111.62,110.45 109.86,112.21 R358.2 109.48,112.58 108.88,113.18 R11.2
$20N117364: length 1.9
  TOP w0.203: U26.1 111.89,111.45 111.58,111.75 R650.2
$21N31413: length 3.1
  TOP w0.254: R404.2 82.26,21.95 U13.7
  TOP w0.381: R404.2 R385.1 C239.1
$21N31414: length 6.8
  TOP w0.203: R387.2 C243.1 ; C243.1 R388.1 ; C243.1 85.69,20.39 85.95,20.66 85.95,21.59 85.19,22.35 85.19,23.72 84.96,23.96 U13.10
$21N31415: length 4
  TOP w0.381: 86.7,25.25 C240.2 84.76,27.23 R389.2
$21N31416: length 1.9
  TOP w0.254: C242.1 84.64,21.81 U13.9
$21N31417: length 2
  TOP w0.254: 84.64,26.21 U13.13
  TOP w0.381: C240.1 83.92,26.92 84.64,26.21
$21N31418: length 1.3
  TOP w0.254: R390.2 81.94,26.82 82.26,26.5 U13.1
$21N31419: length 2.1
  TOP w0.203: C234.1 R386.1
  TOP w0.254: C234.1 83.76,21.72 U13.8
$21N31420: length 2.4
  TOP w0.381: R389.1 83.84,30.27 83.21,29.64 C237.1
$21N31421: length 2
  TOP w0.203: C244.1 C233.1 R386.2
$21N31422: length 2
  TOP w0.381: R384.1 80.03,20.24 80.16,20.37 C239.2 R385.2
$21N31423: length 1
  TOP w0.381: R404.1 81.98,19.88 R403.1
$21N31428: length 1
  TOP w0.203: R407.2 R395.1
$21N31429: length 1.3
  TOP w0.203: R406.1 R407.1
$21N31430: length 1.2
  TOP w0.203: R52.2 77.07,20.66 R392.1
$21N31431: length 2.1
  TOP w0.203: R391.1 R392.2 77.17,21.67 C250.2
$21N31433: length 6.5
  TOP w0.203: R393.2 C260.1 R394.1 v1(74.58,22.08) ; v1(74.73,19.08) 74.68,19.08 74.35,18.75 U14.5
  ART03 w0.254: v1(74.58,22.08) 74.58,19.23 v1(74.73,19.08)
$21N49359: length 2.9
  TOP w0.203: U15.3 88.06,37.72 88.36,38.02 C269.1 R399.1 R402.1
$21N49360: length 1.5
  TOP w0.203: C271.1 87.72,32.97 88.06,33.31 U15.13
$21N49363: length 5.2
  TOP w0.203: 88.14,32.38 87.96,32.21 86.28,32.21 86.23,32.26 R10.2 C262.1 ; 88.14,32.38 R401.1 ; 88.14,32.38 88.14,32.68 88.56,33.1 U15.14
$21N49365: length 1.8
  TOP w0.203: R399.2 C269.2 R396.1
$21N59472: length 3.1
  TOP w0.254: U14.4 74,17.84
  TOP w0.381: 74,17.84 73.66,17.5 71.87,17.5 C251.1
$21N69175: length 3.5
  TOP w0.203: R406.2 R52.1 C250.1
  TOP w0.254: R406.2 74.52,19.63 74.13,19.25 U14.6
$45N4597: length 40.1
  TOP w0.203: LED1.4 94.72,19.3 93.54,20.48 v1(87.6,20.48) ; v1(82.52,38.26) 82.31,38.26 80.01,40.56 74.42,40.56 73.76,41.22 C273.1 R410.2
  ART03 w0.203: v1(82.52,38.26) 84,36.78 84.77,36.78 85.78,35.78 85.78,34.56 86.13,34.21 86.13,21.95 v1(87.6,20.48)
$45N4598: length 34.8
  TOP w0.203: LED1.3 94.75,18.4 93.31,19.85 v1(88.87,19.85) ; R411.2 C274.1 81.05,42.11 81.25,41.91 81.25,40.08 82.35,38.99 83.07,38.99 v1(83.79,38.26)
  ART03 w0.203: v1(83.79,38.26) 84.13,38.26 86.3,36.1 86.3,34.76 86.73,34.33 86.73,22.41 88.87,20.26 v1(88.87,19.85)
$45N4601: length 3.5
  TOP w0.203: R414.2 68.58,39.32 68.91,38.99 C276.1 69.44,39.47 70.1,40.13 Q12.1
$45N4602: length 2.5
  TOP w0.203: R415.2 76,42.21 C277.1 76.89,42.11 77.34,41.66
$45N5400: length 1.3
  TOP w0.203: R417.2 100.71,16.37 D3.2
$45N7206: length 35.4
  TOP w0.203: R418.2 C280.1 88.34,41.1 88.54,40.89 88.54,39.95 88.29,39.7 85.6,39.7 85.06,39.17 v1(85.06,38.26) ; LED3.4 94.64,16.69 94.44,16.89 94.44,17.99 v1(93.09,19.34)
  ART03 w0.203: v1(85.06,38.26) 86.73,36.6 86.73,34.96 87.81,33.88 87.81,22.18 90.65,19.34 v1(93.09,19.34)
$45N7207: length 35
  TOP w0.203: LED3.3 94.4,15.79 93.94,16.25 v1(93.94,17.22) ; R419.2 C281.1 95.57,41.1 95.86,40.8 95.86,39.73 95.58,39.45 v1(95.58,37.91)
  ART03 w0.203: v1(93.94,17.22) 94.18,17.46 94.18,19 89.41,23.77 89.41,35.25 92.07,37.91 v1(95.58,37.91)
$45N7210: length 2.5
  TOP w0.203: Q14.1 84.13,41.1 C283.1 83.23,41.2 R422.2
$45N7211: length 2.5
  TOP w0.203: R423.2 90.47,41.2 C284.1 91.37,41.1 Q15.1
$45N10753: length 1.7
  TOP w0.203: R54.2 94.24,14.13 94.3,14.07 LED4.4
$45N10784: length 1.6
  TOP w0.203: LED4.3 94.27,13.17 94.24,13.2 R290.2
$46N66735: length 73.1
  TOP w0.188: v1(86.89,64.31) 86.88,64.3 C21.2 ; J1.11 120.33,40.9 120.27,40.84 118.35,40.84 v1(118.08,41.11)
  ART03 w0.173: v1(118.08,41.11) 118.35,40.84 119.09,40.84 119.35,41.1 119.35,41.65 119.09,41.91 117.98,41.91 116.52,40.45 112.94,40.45 111.19,42.2 108.65,42.2 107.14,40.69 101.52,40.69 97.28,44.93 90.53,44.93 89.84,44.25 84.09,44.25 81.84,46.5 81.84,52.35 81.58,52.6 81.58,63.65 83.67,65.73 86.18,65.73 86.63,65.28 86.63,64.58 v1(86.89,64.31)
$46N66736: length 73.1
  TOP w0.188: J1.13 120.33,40.39 120.26,40.46 118.36,40.46 v1(118.08,40.18) ; v1(85.97,64.31) 85.98,64.3 C22.2
  ART03 w0.173: v1(85.97,64.31) 86.25,64.59 86.25,65.12 86.02,65.35 83.83,65.35 81.97,63.49 81.97,63.01 82.21,62.76 82.21,62.31 81.97,62.07 81.97,61.62 82.21,61.38 82.21,60.93 81.97,60.68 81.97,60.24 82.21,59.99 82.21,59.55 81.97,59.3 81.97,52.76 82.22,52.51 82.22,46.66 84.25,44.63 89.68,44.63 90.37,45.31 97.43,45.31 101.68,41.07 106.98,41.07 108.49,42.59 111.34,42.59 113.09,40.84 116.36,40.84 117.82,42.29 119.25,42.29 119.73,41.81 119.73,40.94 119.25,40.46 118.36,40.46 v1(118.08,40.18)
$46N66739: length 78.7
  TOP w0.188: v1(88.93,65.53) 88.67,65.28 88.67,63.9 C25.2 ; J1.23 120.33,37.9 120.25,37.82 118.37,37.82 v1(118.08,38.11)
  ART03 w0.173: v1(118.08,38.11) 118.36,37.84 119.16,37.84 119.33,38.01 119.33,38.5 118.99,38.84 109.09,38.84 108.69,39.24 100.79,39.24 96.88,43.15 82.58,43.15 80.34,45.39 80.34,54.03 80.18,54.2 80.18,64.36 82.42,66.6 88.27,66.6 88.67,66.19 88.67,65.79 v1(88.93,65.53)
$46N66740: length 78.6
  TOP w0.188: C26.2 88.29,63.93 88.29,65.24 v1(88,65.53) ; v1(118.08,37.18) 118.34,37.44 120.28,37.44 120.33,37.39 J1.25
  ART03 w0.173: v1(88,65.53) 88.29,65.82 88.29,66.03 88.11,66.22 82.58,66.22 80.56,64.2 80.56,54.35 80.72,54.19 80.72,45.55 82.73,43.54 97.03,43.54 100.95,39.62 108.84,39.62 109.25,39.22 112.14,39.22 112.37,39.45 112.84,39.45 113.06,39.22 113.53,39.22 113.75,39.45 114.22,39.45 114.45,39.22 114.91,39.22 115.14,39.45 115.6,39.45 115.83,39.22 119.15,39.22 119.71,38.65 119.71,37.85 119.31,37.45 118.36,37.45 v1(118.08,37.18)
$46N92195: length 3.5
  TOP w0.203: R16.2 122.73,26.88 122.53,26.68 122.53,26.64 122.28,26.39 J1.69 119.88,26.39 v1(119.66,26.62)
$46N95153: length 2.4
  TOP w0.203: J1.38 114.33,34.14 113.54,34.93 R22.1
$46N95508: length 2.8
  TOP w0.203: J1.50 113.6,31.14 R23.1 113.28,31.65 113.49,31.86 v1(113.9,31.86)
$46N114099: length 86
  TOP w0.188: v1(90.03,64.38) 90.03,64.31 90.04,64.3 C2.2 ; v1(118.08,34.18) 118.35,34.44 120.45,34.44 120.49,34.39 J1.37
  ART03 w0.173: v1(90.03,64.38) 90.14,64.49 90.31,64.66 90.31,65.39 90.31,65.47 88.67,67.11 81.92,67.11 78.92,64.1 78.92,53.16 79.2,52.88 79.2,44.93 81.94,42.19 84.68,42.19 85.08,42.59 96.46,42.59 101.1,37.95 112.93,37.95 114.56,36.32 114.82,36.32 115,36.49 115,36.5 115.17,36.68 115.51,36.68 115.69,36.5 115.69,36.49 115.86,36.32 116.2,36.32 116.38,36.49 116.38,36.5 116.55,36.68 116.9,36.68 117.07,36.5 117.07,36.49 117.24,36.32 119.17,36.32 119.67,35.82 119.67,34.92 119.21,34.45 118.36,34.45 v1(118.08,34.18)
$46N114100: length 86
  TOP w0.188: v1(118.08,35.11) 118.37,34.82 120.45,34.82 120.52,34.9 J1.35 ; v1(90.96,64.38) 90.96,64.31 90.95,64.3 C3.2
  ART03 w0.173: v1(118.08,35.11) 118.36,34.84 119.05,34.84 119.29,35.07 119.29,35.66 119.01,35.94 114.4,35.94 112.78,37.57 100.94,37.57 96.3,42.21 85.24,42.21 84.84,41.81 81.78,41.81 78.82,44.77 78.82,52.72 78.54,53 78.54,64.26 81.76,67.49 88.83,67.49 90.69,65.62 90.69,65.55 90.69,65.55 90.69,64.64 v1(90.96,64.38)
$47N4437: length 5.9
  TOP w0.203: J2.55 8.68,77.36 8.46,77.14 4.55,77.14 v1(4.45,77.04) R43.2
$47N4444: length 34.4
  TOP w0.203: J2.34 13.93,83.39 13.82,83.29 13.82,82.45 13.16,81.79 8.94,81.79 v1(8.18,82.55) ; R46.1 6.1,103.87 v1(5.92,103.69)
  ART03 w0.203: v1(8.18,82.55) 8.1,82.55 4.27,86.38 4.27,89.72 3.07,90.92 3.07,101.64 5.13,103.69 v1(5.92,103.69)
$47N4445: length 38.1
  TOP w0.203: R47.1 2.44,103.87 v1(2.26,103.69) ; J2.22 16.93,83.24 13.84,80.16 8.66,80.16 v1(8.18,80.64)
  ART03 w0.203: v1(8.18,80.64) 8.18,81.22 3.2,86.19 3.2,88.92 2.26,89.86 v1(2.26,103.69)
$47N4481: length 3
  TOP w0.203: J2.53 9.17,77.25 8.59,76.66 v1(8.2,76.66) 7.8,76.66 R70.2
$47N8328: length 2.5
  TOP w0.203: R55.1 20.81,86.82 v1(20.81,86.17) 20.43,85.79 J2.8
$47N8362: length 2.3
  TOP w0.203: R45.1 19.93,86.96 v1(19.93,86.17) J2.10
$47N11242: length 2.7
  TOP w0.203: R59.1 7,86.64 v1(7.28,86.36) 7.93,85.72 J2.58
$47N11243: length 3.9
  TOP w0.203: R58.1 5.6,86.67 5.6,86.08 5.8,85.88 v1(6.68,85.88) 7.07,85.88 7.42,85.52 J2.60
$47N12203: length 2.5
  TOP w0.203: J2.12 19.43,85.67 v1(18.92,86.17) R62.1
$47N12239: length 2.9
  TOP w0.203: J2.14 18.93,85.52 18.62,85.83 18.25,85.83 v1(17.91,86.17) R63.1
$47N17143: length 35.8
  TOP w0.203: v1(3.94,103.69) 4.11,103.87 R68.1 ; v1(9.7,80.64) 10.19,81.13 13.45,81.13 14.81,82.49 14.81,83.16 14.43,83.54 J2.32
  ART03 w0.203: v1(3.94,103.69) 2.67,102.42 2.67,90.03 3.61,89.09 3.61,86.44 9.4,80.64 v1(9.7,80.64)
$47N18593: length 32
  TOP w0.203: v1(9.58,82.55) 12.33,82.55 13.43,83.64 J2.36 ; R69.1 7.72,103.72 v1(7.7,103.69)
  ART03 w0.203: v1(9.58,82.55) 9.16,82.55 5.6,86.11 5.6,88.06 5.78,88.24 5.78,89.81 3.48,92.11 3.48,99.48 v1(7.7,103.69)
$47N36111: length 2.5
  TOP w0.203: J2.20 17.43,85.83 17.02,86.23 R44.1
$47N40951: length 2.4
  TOP w0.188: J2.37 13.17,76.55 12.67,76.05 C42.2
$47N40952: length 2.3
  TOP w0.188: J2.35 13.68,77.33 13.56,77.21 13.56,76.06 C41.2
$47N43343: length 5
  TOP w0.188: J2.3 21.68,79.59 22.58,80.49 24.51,80.49 R416.2
$47N43374: length 6.9
  TOP w0.188: J2.5 21.17,79.63 22.42,80.87 25.15,80.87 R424.2
$49N8755: length 6.1
  TOP w0.203: J10.43 1.93,71.25 1.94,71.25 v1(2.67,71.25) 3.12,71.7 3.12,74.37 3.43,74.68 R427.1
$49N8793: length 4
  TOP w0.203: R428.2 7.42,71.83 v1(6.05,71.83) 5.16,70.95 J10.42
$49N16307: length 13.7
  TOP w0.203: J11.3 130.62,62.99 v1(129.89,63.72) 129.35,64.26 129.35,68.87 128.75,69.47 125.6,69.47 125.25,69.12 R444.1
$49N16308: length 13.7
  TOP w0.203: R445.1 124.66,71.12 125.09,71.12 125.83,71.86 128.86,71.86 129.27,71.45 129.27,69.67 129.8,69.14 129.8,66.6 v1(130.29,66.11) 130.87,65.53 J11.5
$49N16309: length 3.1
  TOP w0.203: R433.2 124.58,70.1 125.03,70.55 v1(125.16,70.55) 125.22,70.61 J11.10
$49N16311: length 10.3
  TOP w0.203: R439.2 124.92,79.94 125.12,79.73 129.2,79.73 129.49,80.02 129.49,81.03 130.54,82.07 v1(130.7,82.07) 131.44,82.07 J11.19
$49N16312: length 11.4
  TOP w0.203: J11.21 131.12,85.85 130.74,85.47 v1(130.74,84.84) 130.74,83.1 129.38,81.74 125.1,81.74 124.84,81.99 R438.2
$49N16313: length 13.3
  TOP w0.203: J11.23 131.25,88.39 130.72,87.86 v1(130.72,87.23) 130.72,86.31 130.11,85.7 130.11,83.33 129.13,82.35 125.2,82.35 R437.2
$49N16315: length 8.6
  TOP w0.203: R435.2 124.77,76.38 125.48,77.09 129.16,77.09 129.67,77.6 129.67,78.23 ; 129.67,78.23 v1(129.67,78.23) ; 129.67,78.23 J11.16
$49N16316: length 2.9
  TOP w0.203: R440.2 125.01,80.96 v1(125.21,80.77) J11.18
$49N16317: length 3.4
  TOP w0.203: J11.24 126.45,88.39 v1(125.23,87.17) R436.2
$49N16328: length 9
  TOP w0.203: J11.37 v1(130.21,106.17) 128.79,104.75 125.25,104.75 125.15,104.65 R452.1
$49N16335: length 16.3
  TOP w0.203: R449.1 125.06,84.08 125.4,84.42 129.04,84.42 129.35,84.73 129.35,85.98 130.19,86.82 130.19,92.79 v1(130.43,93.03) 130.87,93.47 J11.27
$49N16337: length 5.6
  TOP w0.203: R442.2 124.73,90.04 125.33,90.64 v1(125.33,92.42) 125.33,92.97 125.83,93.47 J11.28
$49N16343: length 5.5
  TOP w0.203: R443.2 124.7,101.6 125.28,101.02 125.28,99.87 125.49,99.67 v1(127.02,99.67) 127.35,99.34 J11.32
$49N16344: length 9.1
  TOP w0.203: R453.1 124.98,102.62 125.33,102.26 129.3,102.26 v1(130.67,103.63) J11.35
$49N16346: length 3.3
  TOP w0.203: J11.38 125.41,106.17 v1(124.9,105.66) R455.2
$49N16347: length 5.5
  TOP w0.203: R454.2 125.02,71.81 126.36,73.15 J11.12 129.17,73.15 129.17,73.15 129.36,73.15 v1(129.39,73.13)
$49N16348: length 4.3
  TOP w0.203: J11.40 127.35,108 126.87,107.52 v1(126.64,107.52) 125.86,107.52 125.02,106.68 R456.2
$49N16355: length 8.6
  TOP w0.203: R448.1 125.05,78.96 125.22,79.12 129.63,79.12 v1(130.51,78.23) J11.15
$49N18559: length 2
  TOP w0.203: U22.5 88.5,114.54 R594.2
$49N18560: length 2.6
  TOP w0.203: R595.2 96.37,113.64 v1(95.76,113.03) 95.55,113.24 U22.2
$49N18561: length 2.9
  TOP w0.203: R596.2 v1(95.76,115.06) 95.76,114.14 95.5,113.89 U22.3
$49N18572: length 1.6
  TOP w0.203: U23.5 110.61,115.48 R603.2
$49N18573: length 3.3
  TOP w0.203: R604.2 103.34,116.78 U23.2 105.9,116.78 v1(106.26,117.14)
$49N18574: length 3.9
  TOP w0.203: R605.2 103.34,116.13 U23.3 106.35,116.13 v1(106.76,115.72)
$49N23298: length 4.1
  TOP w0.203: v1(124.23,33.5) 124.23,33.86 124.43,34.06 R253.2 124.92,34.49 125.35,34.92 126.03,34.92 126.5,35.39 U30.6
$49N23299: length 2.8
  TOP w0.203: R252.2 126.47,34.06 126.62,34.21 126.62,34.67 126.93,34.98 v1(126.96,34.98) 127.15,35.17 U30.7
$49N23309: length 2.1
  TOP w0.203: U30.4 125.81,38.73 R254.2
$49N25648: length 14.8
  TOP w0.203: J11.7 130.77,68.07 130.26,68.58 130.26,69.33 129.73,69.86 129.73,72.48 129.97,72.72 129.97,73.46 129.21,74.22 125.67,74.22 125.4,73.95 125.4,73.08 124.99,72.66 R288.1
$49N25997: length 16.3
  TOP w0.203: J11.29 130.87,96.01 129.7,94.84 129.7,87.9 128.77,86.97 125.7,86.97 124.87,86.14 R450.1
$49N29598: length 9.2
  TOP w0.203: R447.1 124.71,74.83 124.94,74.93 125.41,74.93 125.6,74.74 129.41,74.74 131,73.15 J11.11
$49N29990: length 3.1
  TOP w0.203: J11.36 R258.2
$49N30030: length 3.2
  TOP w0.203: J11.22 125.64,85.85 124.9,85.11 R289.2
$49N33582: length 2.9
  TOP w0.203: J11.8 125.62,68.07 125.43,68.26 R51.2
$49N34084: length 48.9
  TOP w0.203: J11.31 v1(129.78,98.55) ; R21.1 v1(109.09,75.31)
  ART04 w0.203: v1(109.09,75.31) 109.7,74.7 118.76,74.7 119.6,73.86 126.4,73.86 127.86,75.33 127.86,90.04 126.17,91.73 126.17,92.29 128.17,94.29 128.17,96.94 v1(129.78,98.55)
$49N34222: length 39.6
  TOP w0.203: J11.26 127.35,91.2 v1(126.63,91.92) ; R29.2 v1(109.09,74.3)
  ART04 w0.203: v1(126.63,91.92) 128.27,90.28 128.27,75.16 126.57,73.45 119.43,73.45 118.59,74.3 v1(109.09,74.3)
$49N34367: length 18.7
  TOP w0.203: J11.33 130.87,101.09 129.28,99.5 129.28,90.07 128.68,89.46 125.28,89.46 124.95,89.12 R56.1
$49N34520: length 9.3
  TOP w0.203: R57.1 124.81,75.51 125.15,75.84 125.15,76.18 125.61,76.64 129.87,76.64 130.82,75.69 J11.13
$49N38048: length 4.2
  TOP w0.203: J10.47 1.99,72.45 2.59,73.05 2.59,74.76 2.41,74.94 R426.1
$49N38251: length 3.9
  TOP w0.203: J10.46 5.09,72.15 5.97,73.03 R425.2
$50N4470: length 2.1
  TOP w0.203: SW1.6 130.53,44.89 R470.1
$50N4927: length 1.5
  TOP w0.203: U16.4 98.2,45.31 C289.1
$50N4929: length 6.7
  TOP w0.203: U16.3 103.56,45.31 103.63,45.39 R478.1 104.19,45.8 104.52,46.13 107.77,46.13 Q16.3
$50N5621: length 1.4
  TOP w0.203: R479.1 107.16,43.44 Q16.1
$50N7178: length 2.2
  TOP w0.203: R469.1 132.44,44.69 SW1.5
$50N10237: length 2.5
  TOP w0.203: R471.1 128.75,44.13 SW1.7
$50N10250: length 2.7
  TOP w0.203: SW1.8 126.85,43.49 R472.1
$51N171791: length 1.8
  TOP w0.203: R237.2 119.73,58.26 U20.3
$51N171792: length 1.8
  TOP w0.203: R635.2 119.08,58.25 U20.2
$51N172159: length 1.9
  TOP w0.203: R575.2 120.38,58.54 U20.4
$51N172500: length 2.1
  TOP w0.203: R637.2 121.74,58.27 121.03,58.98 U20.5
$51N175745: length 2.7
  TOP w0.203: U32.5 115.12,58.95 115.39,58.68 115.93,58.68 R638.2
$51N176453: length 2.3
  TOP w0.203: U32.4 114.47,58.95 115.36,58.06 R669.2
$51N176454: length 2.1
  TOP w0.203: U32.3 113.82,58.49 114.25,58.06 R674.2
$51N176455: length 1.8
  TOP w0.203: R636.2 113.17,58.11 U32.2
$51N179684: length 2.5
  TOP w0.203: U20.8 122.33,64.99 122.66,64.66 R589.1
$51N179736: length 1.7
  TOP w0.203: U32.8 116.42,67.51 R591.1
$51N184426: length 14.2
  TOP w0.203: U24.3 v1(81.6,77.81) ; R622.2 v1(70.35,75.26)
  ART03 w0.203: v1(81.6,77.81) 77.46,77.81 76.5,76.85 71.94,76.85 v1(70.35,75.26)
$51N184427: length 11.7
  TOP w0.203: R623.2 v1(73.77,73.05) ; v1(80.3,76.91) 80.75,76.91 81.01,77.16 U24.2
  ART03 w0.203: v1(73.77,73.05) 74.1,73.37 74.1,73.59 77.52,77.01 80.19,77.01 v1(80.3,76.91)
$51N184759: length 36.2
  TOP w0.203: v1(106.55,80.85) 106.55,80.92 106.93,81.3 R291.2 ; U24.4 v1(80.3,78.46)
  ART04 w0.203: v1(106.55,80.85) 104.32,78.61 101.44,78.61 99.13,80.92 91.19,80.92 89.15,78.89 86.6,78.89 86.32,78.61 85.18,78.61 83.76,79.2 82.08,80.88 80.42,80.88 79.69,80.14 79.69,79.63 80.3,79.03 v1(80.3,78.46)
$51N185068: length 36.7
  TOP w0.203: U24.5 v1(81.6,79.11) ; R626.2 109.7,77.55 110.37,78.21 v1(110.77,78.21)
  ART04 w0.203: v1(81.6,79.11) 81.61,79.11 85.21,75.51 85.59,75.51 86.5,76.43 88.71,76.43 89.27,76.98 89.27,77.2 91.77,79.71 92.5,79.71 93.97,78.23 97.41,78.23 98.25,77.39 105.44,77.39 106.26,78.21 v1(110.77,78.21)
$51N185452: length 1.8
  TOP w0.203: R614.1 75.93,77.81 U24.12
$51N185453: length 1.6
  TOP w0.203: R615.1 75.47,77.16 U24.13
$51N185799: length 1.7
  TOP w0.203: R618.1 75.69,79.11 U24.10
$51N186799: length 1.7
  TOP w0.203: R628.1 75.52,80.41 U24.8
$51N188619: length 1.9
  TOP w0.203: U25.12 76.03,83.73 75.43,83.12 R617.1
$51N188623: length 1.7
  TOP w0.203: R613.1 75.64,84.83 75.83,85.03 U25.10
$51N188624: length 1.8
  TOP w0.203: R616.1 75.6,83.98 76,84.38 U25.11
$51N189028: length 4.9
  TOP w0.203: R621.2 84.64,86.42 84.28,86.06 84.28,85.23 84.07,85.03 U25.5
$51N189029: length 23.3
  TOP w0.203: R624.2 v1(71.21,71.01) ; U25.4 v1(81.68,84.38)
  ART03 w0.203: v1(81.68,84.38) 83.08,82.97 83.08,81.22 82.51,80.66 82.51,78.05 80.82,76.35 78,76.35 73.41,71.75 71.95,71.75 v1(71.21,71.01)
